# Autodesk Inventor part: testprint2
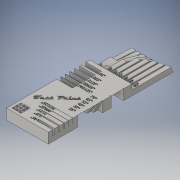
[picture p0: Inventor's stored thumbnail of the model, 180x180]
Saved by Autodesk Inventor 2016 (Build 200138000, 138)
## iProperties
Created: 2017-02
Part Number: testprint2
Material: Generic
Document SubType Name: Modeling
Designer: Corey
Density: 1 g/cm^3
Appearance: Default
Author: Corey
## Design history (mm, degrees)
sketch "Sketch1"
  geometry: L1 (0, 0)-(2.54, 0); L2 (2.54, 0)-(2.54, -76.2); L3 (2.54, -76.2)-(0, -76.2); L4 (0, -76.2)-(0, 0)
  constraints: 8 end point, 2 parallel, 1 horizontal, 1 perpendicular
  dimensions: "d0" = 76.2 distance between parallel lines of L3 L1 (= 3 x n); "d1" = 2.54 distance of L1.start L1.end (= 0.1 x n)
extrude "Extrusion1" new body sketch "Sketch1" distance "d2" = 3.175 (= 0.125 x n); taper "d3" = 0 deg
pattern_linear "Rectangular Pattern1" dims "d6" = 3.26571 (= 1.28571 x d1)
chamfer "Chamfer1" distance "d7" = 3.175 (= 0.125 x n); stored, may be unused: second distance "d8" = 3.175, angle "d9" = 25 deg
chamfer "Chamfer2" distance "d10" = 3.175 (= 0.125 x n); stored, may be unused: second distance "d11" = 3.175, angle "d12" = 35 deg
chamfer "Chamfer3" distance "d13" = 3.175 (= 0.125 x n); stored, may be unused: second distance "d14" = 3.175, angle "d15" = 45 deg
chamfer "Chamfer4" distance "d16" = 3.175 (= 0.125 x n); stored, may be unused: second distance "d17" = 3.175, angle "d18" = 55 deg
chamfer "Chamfer5" distance "d19" = 3.175 (= 0.125 x n); stored, may be unused: second distance "d20" = 3.175, angle "d21" = 65 deg
chamfer "Chamfer6" distance "d22" = 3.175 (= 0.125 x n); stored, may be unused: second distance "d23" = 3.175, angle "d24" = 75 deg
chamfer "Chamfer7" distance "d25" = 3.175 (= 0.125 x n); stored, may be unused: second distance "d26" = 3.175, angle "d27" = 85 deg
chamfer "Chamfer8" distance "d28" = 3.175 (= 0.125 x n); stored, may be unused: second distance "d29" = 3.175, angle "d30" = 87.5 deg
sketch "Sketch2"
  geometry: L1 (-25.4, 0)-(-25.4, -76.2) reference; L2 (0, 0)-(-25.4, 0); L3 (-25.4, 0)-(-25.4, -50.8); L4 (-25.4, -50.8)-(0, -50.8); L5 (0, -50.8)-(0, 0)
  constraints: 8 end point, 2 parallel, 1 horizontal, 1 perpendicular, 1 point on line
  dimensions: "d31" = 50.8 distance of L3.end L2.end (= 2 x n)
extrude "Extrusion2" join sketch "Sketch2" distance "d32" = 6.35 (= 0.25 x n); taper "d33" = 0 deg
sketch "Sketch7"
  geometry: L1 (-25.4, -50.8)-(-22.86, -50.8) reference; L2 (-25.4, -50.8)-(0, -50.8); L3 (0, -50.8)-(0, -63.5); L4 (0, -63.5)-(-25.4, -63.5); L5 (-25.4, -63.5)-(-25.4, -50.8); 1 further point
  constraints: 8 end point, 2 parallel, 1 horizontal, 1 perpendicular
extrude "Extrusion3" join sketch "Sketch7" distance "d56" = 1.5875 (= 0.0625 x n); taper "d57" = 0 deg
sketch "Sketch6"
  geometry: L1 (-2.032, 53.34)-(-2.032, 56.084); L2 (-2.032, 56.084)-(-0.444, 56.084); L3 (-0.444, 56.084)-(-0.444, 53.34); L4 (-0.444, 53.34)-(-2.032, 53.34); L5 (-2.54, 50.8)-(-2.54, 76.2) reference; L6 (-3.709, 53.34)-(-5.298, 53.34); L7 (-5.298, 53.34)-(-5.298, 56.084); L8 (-5.298, 56.084)-(-3.709, 56.084); L9 (-3.709, 56.084)-(-3.709, 53.34); L10 (-6.975, 53.34)-(-8.563, 53.34); L11 (-8.563, 53.34)-(-8.563, 56.084); L12 (-8.563, 56.084)-(-6.975, 56.084); L13 (-6.975, 56.084)-(-6.975, 53.34); L14 (-10.241, 53.34)-(-11.829, 53.34); L15 (-11.829, 53.34)-(-11.829, 56.084); L16 (-11.829, 56.084)-(-10.241, 56.084); L17 (-10.241, 56.084)-(-10.241, 53.34); L18 (-13.507, 53.34)-(-15.095, 53.34); L19 (-15.095, 53.34)-(-15.095, 56.084); L20 (-15.095, 56.084)-(-13.507, 56.084); L21 (-13.507, 56.084)-(-13.507, 53.34); L22 (-16.772, 53.34)-(-18.361, 53.34); L23 (-18.361, 53.34)-(-18.361, 56.084); L24 (-18.361, 56.084)-(-16.772, 56.084); L25 (-16.772, 56.084)-(-16.772, 53.34); L26 (-20.038, 53.34)-(-21.626, 53.34); L27 (-21.626, 53.34)-(-21.626, 56.084); L28 (-21.626, 56.084)-(-20.038, 56.084); L29 (-20.038, 56.084)-(-20.038, 53.34); L30 (-23.304, 53.34)-(-24.892, 53.34); L31 (-24.892, 53.34)-(-24.892, 56.084); L32 (-24.892, 56.084)-(-23.304, 56.084); L33 (-23.304, 56.084)-(-23.304, 53.34); L34 (-25.4, 76.2)-(-25.4, 50.8) reference; L35 (-22.134, 50.8)-(-22.134, 76.2) reference; L36 (-18.869, 64.351)-(-18.869, 50.8) reference; L37 (-15.603, 50.8)-(-15.603, 76.2) reference; L38 (-12.337, 50.8)-(-12.337, 76.2) reference; L39 (-9.071, 50.8)-(-9.071, 76.2) reference; L40 (-5.806, 73.977)-(-5.806, 50.8) reference; 2 further points
  constraints: 17 other
  dimensions: "d45" = 0.508 distance between parallel lines of L5 L1 (= 0.02 x n); "d46" = 2.54 dimension on L4 (= 0.1 x n); "d47" = 0.508 distance between parallel lines of L34 L31 (= d45); "d48" = 0.508 distance between parallel lines of L35 L27 (= d45); "d49" = 0.508 distance between parallel lines of L36 L23 (= d45); "d50" = 0.508 distance between parallel lines of L37 L19 (= d45); "d51" = 0.508 distance between parallel lines of L38 L15 (= 0.02 x n); "d52" = 0.508 distance between parallel lines of L39 L11 (= 0.02 x n); "d53" = 0.508 distance between parallel lines of L40 L7 (= 0.02 x n)
emboss "Emboss2" sketch "Sketch6" dims "d0" = 76.2 (= 3 x n), "d1" = 2.54 (= 0.1 x n), "d54" = 0.508, "d55" = 0
sketch "Sketch8"
  geometry: L1 (-25.4, 48.26)-(-15.875, 48.26); L2 (-15.875, 48.26)-(-15.875, 45.72); L3 (-15.875, 45.72)-(-25.4, 45.72); L4 (-25.4, 45.72)-(-25.4, 48.26); L5 (0, 50.8)-(-25.4, 50.8) reference; L6 (-25.4, 48.26)-(-15.875, 48.26); L7 (-15.875, 48.26)-(-15.875, 45.72); L8 (-15.875, 45.72)-(-25.4, 45.72); L9 (-25.4, 45.72)-(-25.4, 48.26); L10 (-25.4, 44.45)-(-15.875, 44.45); L11 (-15.875, 44.45)-(-15.875, 41.91); L12 (-15.875, 41.91)-(-25.4, 41.91); L13 (-25.4, 41.91)-(-25.4, 44.45); L14 (-25.4, 41.275)-(-15.875, 41.275); L15 (-15.875, 41.275)-(-15.875, 38.735); L16 (-15.875, 38.735)-(-25.4, 38.735); L17 (-25.4, 38.735)-(-25.4, 41.275); L18 (-25.4, 38.417)-(-15.875, 38.417); L19 (-15.875, 38.417)-(-15.875, 35.877); L20 (-15.875, 35.877)-(-25.4, 35.877); L21 (-25.4, 35.877)-(-25.4, 38.417); L22 (-25.4, 35.719)-(-15.875, 35.719); L23 (-15.875, 35.719)-(-15.875, 33.179); L24 (-15.875, 33.179)-(-25.4, 33.179); L25 (-25.4, 33.179)-(-25.4, 35.719); L26 (-25.4, 33.099)-(-15.875, 33.099); L27 (-15.875, 33.099)-(-15.875, 30.559); L28 (-15.875, 30.559)-(-25.4, 30.559); L29 (-25.4, 30.559)-(-25.4, 33.099); 1 further point
  constraints: 56 end point, 14 parallel, 7 horizontal, 7 perpendicular
  dimensions: "d58" = 9.525 distance of L2.end L3.end (= 0.375 x n); "d59" = 2.54 distance of L1.end L2.end; "d60" = 2.54 distance between parallel lines of L5 L1; "d80" = 9.525 distance of L7.end L8.end (derived); "d81" = 2.54 distance of L6.end L7.end; "d83" = 9.525 distance of L11.end L12.end (derived); "d84" = 2.54 distance of L10.end L11.end; "d86" = 9.525 distance of L15.end L16.end (derived); "d87" = 2.54 distance of L14.end L15.end; "d89" = 9.525 distance of L19.end L20.end (derived); "d90" = 2.54 distance of L18.end L19.end; "d92" = 9.525 distance of L23.end L24.end (derived); "d93" = 2.54 distance of L22.end L23.end; "d95" = 9.525 distance of L27.end L28.end (derived); "d96" = 2.54 distance of L26.end L27.end; "d101" = 1.27 distance between parallel lines of L10 L3; "d102" = 0.635 distance between parallel lines of L14 L12; "d103" = 0.3175 distance between parallel lines of L18 L16; "d104" = 0.15875 distance between parallel lines of L22 L20; "d105" = 0.07938 distance between parallel lines of L26 L24
extrude "Extrusion4" cut sketch "Sketch8" stored distance "d61" = 1.5875 (= 0.0625 x n); taper "d62" = 0 deg
sketch "Sketch11"
  geometry: L1 (-15.875, 47.344)-(-11.111, 47.344); L2 (-11.111, 47.344)-(-11.111, 45.72); L3 (-11.111, 45.72)-(-15.875, 45.72); L4 (-15.875, 45.72)-(-15.875, 47.344); L5 (-15.875, 45.72)-(-25.4, 45.72) reference; L6 (-15.875, 48.26)-(-15.875, 45.72) reference; L7 (-15.875, 41.91)-(-15.875, 43.534); L8 (-15.875, 43.534)-(-11.111, 43.534); L9 (-11.111, 43.534)-(-11.111, 41.91); L10 (-11.111, 41.91)-(-15.875, 41.91); L11 (-15.875, 38.735)-(-15.875, 40.359); L12 (-15.875, 40.359)-(-11.111, 40.359); L13 (-11.111, 40.359)-(-11.111, 38.735); L14 (-11.111, 38.735)-(-15.875, 38.735); L15 (-15.875, 35.877)-(-15.875, 37.502); L16 (-15.875, 37.502)-(-11.111, 37.502); L17 (-11.111, 37.502)-(-11.111, 35.877); L18 (-11.111, 35.877)-(-15.875, 35.877); L19 (-15.875, 33.179)-(-15.875, 34.803); L20 (-15.875, 34.803)-(-11.111, 34.803); L21 (-11.111, 34.803)-(-11.111, 33.179); L22 (-11.111, 33.179)-(-15.875, 33.179); L23 (-15.875, 41.91)-(-25.4, 41.91) reference; L24 (-15.875, 38.735)-(-25.4, 38.735) reference; L25 (-15.875, 35.877)-(-25.4, 35.877) reference; L26 (-15.875, 33.179)-(-25.4, 33.179) reference; 1 further point
  constraints: 6 collinear, 10 other
emboss "Emboss4" sketch "Sketch11" dims "d0" = 76.2 (= 3 x n), "d1" = 2.54 (= 0.1 x n), "d106" = 0.508, "d107" = 0
sketch "Sketch12"
  geometry: L1 (0, 0)-(0, 50.8) reference; L2 (0, 2.54)-(-9.525, 2.54); L3 (-9.525, 2.54)-(-9.525, 3.81); L4 (-9.525, 3.81)-(0, 3.81); L5 (0, 3.81)-(0, 2.54); L6 (-25.4, 0)-(0, 0) reference; L7 (0, 6.35)-(-9.525, 6.35); L8 (-9.525, 6.35)-(-9.525, 6.985); L9 (-9.525, 6.985)-(0, 6.985); L10 (0, 6.985)-(0, 6.35); L11 (0, 9.525)-(-9.525, 9.525); L12 (-9.525, 9.525)-(-9.525, 9.684); L13 (-9.525, 9.684)-(0, 9.684); L14 (0, 9.684)-(0, 9.525); L15 (0, 12.224)-(-9.525, 12.224); L16 (-9.525, 12.224)-(-9.525, 12.306); L17 (-9.525, 12.306)-(0, 12.306); L18 (0, 12.306)-(0, 12.224); L19 (0, 14.846)-(-9.525, 14.846); L20 (-9.525, 14.846)-(-9.525, 14.886); L21 (-9.525, 14.886)-(0, 14.886); L22 (0, 14.886)-(0, 14.846)
  constraints: 40 end point, 10 parallel, 5 horizontal, 5 perpendicular, 1 point on line
  dimensions: "d108" = 9.525 distance of L3.end L4.end (derived); "d109" = 1.27 distance of L2.end L3.end; "d110" = 2.54 distance between parallel lines of L6 L2; "d114" = 9.525 distance of L8.end L9.end (derived); "d115" = 0.635 distance of L7.end L8.end; "d117" = 9.525 distance of L12.end L13.end (derived); "d118" = 0.15875 distance of L11.end L12.end; "d120" = 9.525 distance of L16.end L17.end (derived); "d121" = 0.08255 distance of L15.end L16.end; "d123" = 9.525 distance of L20.end L21.end (derived); "d124" = 0.03969 distance of L19.end L20.end; "d138" = 2.54 distance between parallel lines of L7 L4; "d139" = 2.54 distance between parallel lines of L11 L9; "d140" = 2.54 distance between parallel lines of L15 L13; "d141" = 2.54 distance between parallel lines of L19 L17
extrude "Extrusion5" cut sketch "Sketch12" stored distance "d145" = 1.5875 (derived); taper "d146" = 0 deg
sketch "Sketch13"
  geometry: L1 (-9.525, 2.186)-(-14.432, 2.186); L2 (-14.432, 2.186)-(-14.432, 3.81); L3 (-14.432, 3.81)-(-9.525, 3.81); L4 (-9.525, 3.81)-(-9.525, 2.186); L5 (-9.525, 2.54)-(-9.525, 3.81) reference; L6 (-9.525, 3.81)-(0, 3.81) reference; L7 (-9.525, 6.985)-(-9.525, 5.361); L8 (-9.525, 5.361)-(-14.432, 5.361); L9 (-14.432, 5.361)-(-14.432, 6.985); L10 (-14.432, 6.985)-(-9.525, 6.985); L11 (-9.525, 9.684)-(-9.525, 8.06); L12 (-9.525, 8.06)-(-14.432, 8.06); L13 (-14.432, 8.06)-(-14.432, 9.684); L14 (-14.432, 9.684)-(-9.525, 9.684); L15 (-9.525, 12.306)-(-9.525, 10.682); L16 (-9.525, 10.682)-(-14.432, 10.682); L17 (-14.432, 10.682)-(-14.432, 12.306); L18 (-14.432, 12.306)-(-9.525, 12.306); L19 (-9.525, 14.886)-(-9.525, 13.262); L20 (-9.525, 13.262)-(-14.432, 13.262); L21 (-14.432, 13.262)-(-14.432, 14.886); L22 (-14.432, 14.886)-(-9.525, 14.886); L23 (-9.525, 6.985)-(0, 6.985) reference; L24 (-9.525, 9.684)-(0, 9.684) reference; L25 (-9.525, 12.306)-(0, 12.306) reference; L26 (-9.525, 14.886)-(0, 14.886) reference; 1 further point
  constraints: 6 collinear, 10 other
emboss "Emboss5" sketch "Sketch13" dims "d0" = 76.2 (= 3 x n), "d1" = 2.54 (= 0.1 x n), "d147" = 0.508, "d148" = 0
sketch "Sketch14" dims "d157" = 25.4
  geometry: L1 (33.02, 6.35)-(30.48, 6.35); L2 (30.48, 6.35)-(30.48, -19.05); L3 (30.48, -19.05)-(33.02, -19.05); L4 (33.02, -19.05)-(33.02, 6.35); L5 (50.8, 3.175)-(50.8, 6.35) reference; L6 (30.48, 6.35)-(27.94, 6.35); L7 (27.94, 6.35)-(27.94, -19.05); L8 (27.94, -19.05)-(30.48, -19.05); L9 (30.48, -19.05)-(30.48, 6.35); L10 (27.94, 6.35)-(25.4, 6.35); L11 (25.4, 6.35)-(25.4, -19.05); L12 (25.4, -19.05)-(27.94, -19.05); L13 (27.94, -19.05)-(27.94, 6.35); L14 (25.4, 6.35)-(22.86, 6.35); L15 (22.86, 6.35)-(22.86, -19.05); L16 (22.86, -19.05)-(25.4, -19.05); L17 (25.4, -19.05)-(25.4, 6.35); L18 (22.86, 6.35)-(20.32, 6.35); L19 (20.32, 6.35)-(20.32, -19.05); L20 (20.32, -19.05)-(22.86, -19.05); L21 (22.86, -19.05)-(22.86, 6.35); L22 (20.32, 6.35)-(17.78, 6.35); L23 (17.78, 6.35)-(17.78, -19.05); L24 (17.78, -19.05)-(20.32, -19.05); L25 (20.32, -19.05)-(20.32, 6.35); 1 further point
  constraints: 48 end point, 2 horizontal, 2 parallel, 1 collinear, 1 perpendicular, 39 other
  dimensions: "d149" = 2.54 distance of L3.end L2.end (derived); "d150" = 25.4 distance of L2.end L1.end (derived); "d151" = 17.78 distance between parallel lines of L4 L5 (derived); "d154" = 2.54 distance of L1.start L6.start (derived)
revolve "Revolution1" stored, may be unused: angle "d159" = 25 deg
revolve "Revolution2" stored, may be unused: angle "d160" = 35 deg
revolve "Revolution3" stored, may be unused: angle "d161" = 45 deg
revolve "Revolution4" stored, may be unused: angle "d162" = 55 deg
revolve "Revolution5" stored, may be unused: angle "d163" = 65 deg
revolve "Revolution6" stored, may be unused: angle "d164" = 75 deg
sketch "Sketch15"
  geometry: L1 (-30.761, 33.501)-(-24.818, 33.501); L2 (-24.818, 33.501)-(-24.818, 27.577); L3 (-24.818, 27.577)-(-30.761, 27.577); L4 (-30.761, 27.577)-(-30.761, 33.501); L5 (-23.813, 1.587)-(-22.288, 1.587); L6 (-22.288, 1.587)-(-22.288, 3.111); L7 (-22.288, 3.111)-(-23.812, 3.111); L8 (-23.812, 3.111)-(-23.813, 1.587); L9 (-23.813, 1.587)-(-22.288, 3.111); L10 (-22.288, 1.587)-(-23.812, 3.111); L11 (-23.813, 3.619)-(-22.288, 3.619); L12 (-22.288, 3.619)-(-22.288, 5.143); L13 (-22.288, 5.143)-(-23.812, 5.143); L14 (-23.812, 5.143)-(-23.813, 3.619); L15 (-23.813, 3.619)-(-22.288, 5.143); L16 (-22.288, 3.619)-(-23.812, 5.143); L17 (-23.813, 5.651)-(-22.288, 5.651); L18 (-22.288, 5.651)-(-22.288, 7.175); L19 (-22.288, 7.175)-(-23.812, 7.175); L20 (-23.812, 7.175)-(-23.813, 5.651); L21 (-23.813, 5.651)-(-22.288, 7.175); L22 (-22.288, 5.651)-(-23.812, 7.175); L23 (-21.781, 1.587)-(-20.257, 1.587); L24 (-20.257, 1.587)-(-20.257, 3.111); L25 (-20.257, 3.111)-(-21.781, 3.111); L26 (-21.781, 3.111)-(-21.781, 1.587); L27 (-21.781, 1.587)-(-20.257, 3.111); L28 (-20.257, 1.587)-(-21.781, 3.111); L29 (-21.781, 3.619)-(-20.257, 3.619); L30 (-20.257, 3.619)-(-20.257, 5.143); L31 (-20.257, 5.143)-(-21.781, 5.143); L32 (-21.781, 5.143)-(-21.781, 3.619); L33 (-21.781, 3.619)-(-20.257, 5.143); L34 (-20.257, 3.619)-(-21.781, 5.143); L35 (-21.781, 5.651)-(-20.257, 5.651); L36 (-20.257, 5.651)-(-20.257, 7.175); L37 (-20.257, 7.175)-(-21.781, 7.175); L38 (-21.781, 7.175)-(-21.781, 5.651); L39 (-21.781, 5.651)-(-20.257, 7.175); L40 (-20.257, 5.651)-(-21.781, 7.175); L41 (-19.749, 1.587)-(-18.225, 1.587); L42 (-18.225, 1.587)-(-18.225, 3.111); L43 (-18.225, 3.111)-(-19.749, 3.111); L44 (-19.749, 3.111)-(-19.749, 1.587); L45 (-19.749, 1.587)-(-18.225, 3.111); L46 (-18.225, 1.587)-(-19.749, 3.111); L47 (-19.749, 3.619)-(-18.225, 3.619); L48 (-18.225, 3.619)-(-18.225, 5.143); L49 (-18.225, 5.143)-(-19.749, 5.143); L50 (-19.749, 5.143)-(-19.749, 3.619); L51 (-19.749, 3.619)-(-18.225, 5.143); L52 (-18.225, 3.619)-(-19.749, 5.143); L53 (-19.749, 5.651)-(-18.225, 5.651); L54 (-18.225, 5.651)-(-18.225, 7.175); L55 (-18.225, 7.175)-(-19.749, 7.175); L56 (-19.749, 7.175)-(-19.749, 5.651); L57 (-19.749, 5.651)-(-18.225, 7.175); L58 (-18.225, 5.651)-(-19.749, 7.175); C1 r 0.762 at (-23.05, 6.413); C2 r 0.762 at (-21.019, 4.381); 10 further points; 1 other entity
  constraints: 108 end point, 22 midpoint, 2 centre point, 2 collinear, 2 horizontal, 2 parallel, 1 perpendicular, 1 vertical, 88 other
  dimensions: "d185" = 1.524 distance of L7.end L6.end; "d186" = 1.524 distance of L6.end L5.end; "d196" = 2.032 distance of L5.start L11.start; "d199" = 2.032 distance of L5.start L23.start; "d207" = 1.524 diameter of C1; "d208" = 1.524 diameter of C2
extrude "Extrusion6" cut sketch "Sketch15" distance "d211" = 1.5875; taper "d212" = 0 deg
sketch "Sketch17"
  geometry: L1 (-6.065, 32.836)-(-2.79, 32.836); L2 (-2.79, 32.836)-(-2.79, 31.254); L3 (-2.79, 31.254)-(-6.065, 31.254); L4 (-6.065, 31.254)-(-6.065, 32.836); L5 (-6.065, 28.58)-(-6.065, 30.162); L6 (-6.065, 30.162)-(-2.79, 30.162); L7 (-2.79, 30.162)-(-2.79, 28.58); L8 (-2.79, 28.58)-(-6.065, 28.58); L9 (-6.065, 26.017)-(-6.065, 27.599); L10 (-6.065, 27.599)-(-2.79, 27.599); L11 (-2.79, 27.599)-(-2.79, 26.017); L12 (-2.79, 26.017)-(-6.065, 26.017); L13 (-6.065, 23.502)-(-6.065, 25.084); L14 (-6.065, 25.084)-(-2.79, 25.084); L15 (-2.79, 25.084)-(-2.79, 23.502); L16 (-2.79, 23.502)-(-6.065, 23.502); L17 (-6.065, 20.928)-(-6.065, 22.51); L18 (-6.065, 22.51)-(-2.79, 22.51); L19 (-2.79, 22.51)-(-2.79, 20.928); L20 (-2.79, 20.928)-(-6.065, 20.928); L21 (-6.065, 18.324)-(-6.065, 19.906); L22 (-6.065, 19.906)-(-2.79, 19.906); L23 (-2.79, 19.906)-(-2.79, 18.324); L24 (-2.79, 18.324)-(-6.065, 18.324); 1 further point
  constraints: 12 other
emboss "Emboss6" sketch "Sketch17" dims "d0" = 76.2 (= 3 x n), "d1" = 2.54 (= 0.1 x n), "d221" = 0.508, "d222" = 0
sketch "Sketch18"
  geometry: L1 (-23.812, 14.92)-(-5.643, 31.634); L2 (-5.643, 31.634)-(-3.601, 29.414); L3 (-3.601, 29.414)-(-21.77, 12.7); L4 (-21.77, 12.7)-(-23.812, 14.92); 1 further point
  constraints: 2 other
emboss "Emboss7" sketch "Sketch18" dims "d0" = 76.2 (= 3 x n), "d1" = 2.54 (= 0.1 x n), "d223" = 0.508, "d224" = 0
sketch "Sketch19"
  geometry: L1 (-4.931, 3.175)-(-4.931, 2.667) reference; L2 (-4.931, 3.175)-(-12.551, 3.175); L3 (-12.551, 3.175)-(-12.551, -3.175); L4 (-12.551, -3.175)-(-4.931, -3.175); L5 (-4.931, -3.175)-(-4.931, 3.175); 1 further point
  constraints: 8 end point, 2 parallel, 1 horizontal, 1 perpendicular
  dimensions: "d225" = 7.62 distance of L4.end L3.end (derived)
revolve "Revolution7" sketch "Sketch19" stored, may be unused: angle "d226" = 90 deg
body "Solid1"
node "Image1"
other parameters: "n" = 25.4 [user parameter; used in 21 equation terms], "d82" = 25.4 [user parameter], "d85" = 25.4 [user parameter], "d88" = 25.4 [user parameter], "d91" = 25.4 [user parameter], "d94" = 25.4 [user parameter], "d97" = 25.4 [user parameter], "d100" = 25.4 [user parameter], "d113" = 25.4 [user parameter], "d116" = 25.4 [user parameter], "d119" = 25.4 [user parameter], "d122" = 25.4 [user parameter], "d125" = 25.4 [user parameter], "d128" = 25.4 [user parameter], "d131" = 25.4 [user parameter], "d134" = 25.4 [user parameter], "d137" = 25.4 [user parameter]
